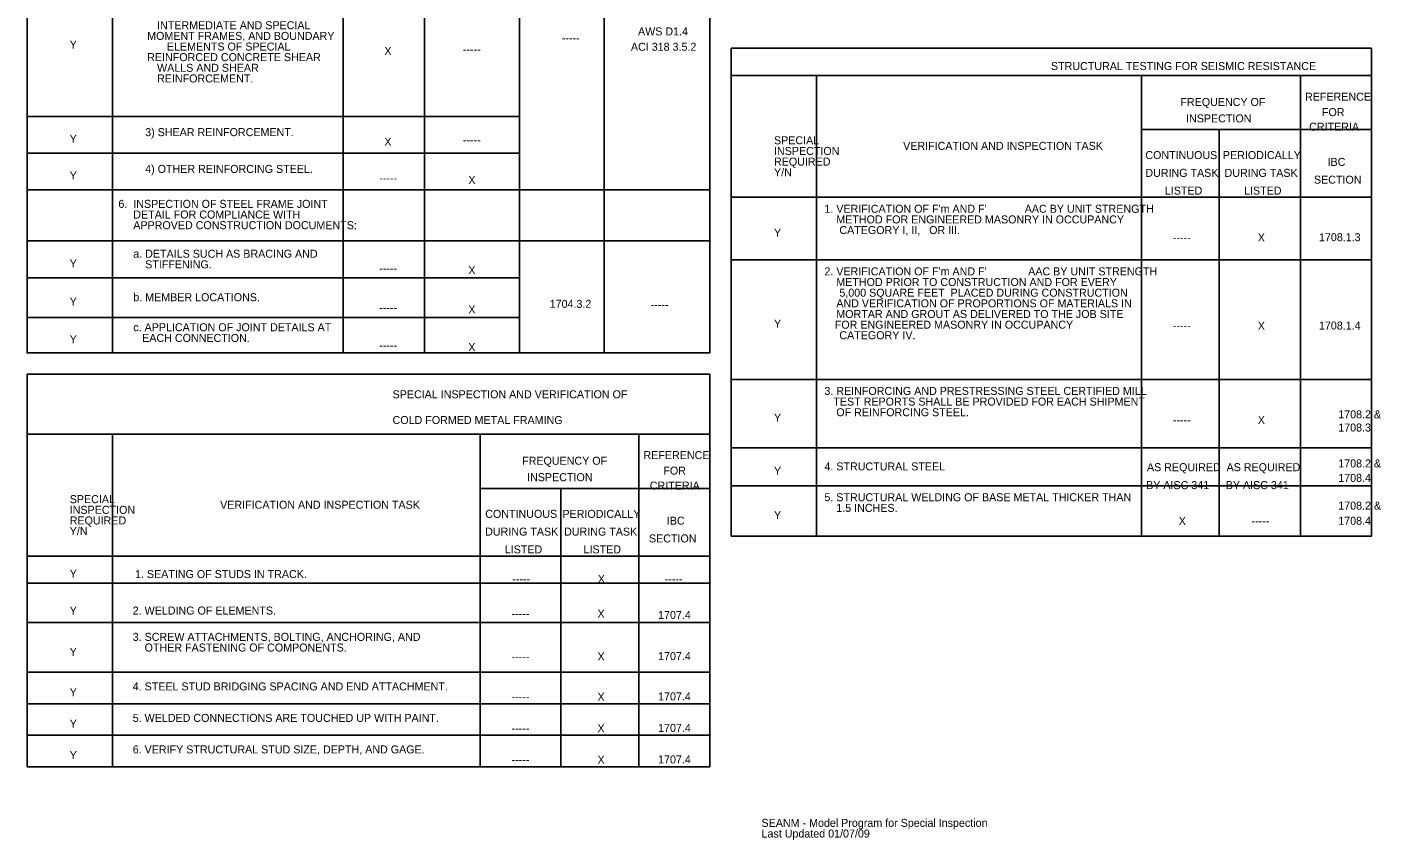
# Model space of a CAD drawing. Extents: x 2632118 to 2632142.4, y 1706724.1 to 1706788.4.
# Drawn here: x 2632128.03 to 2632142.13, y 1706769.54 to 1706778 of the extents above; entities that cross this region are included whole.
import ezdxf

# ---------------------------------------------------------------- set-up
doc = ezdxf.new("R2010")
doc.units = 0
doc.layers.add('Default', color=7, linetype='Continuous')

msp = doc.modelspace()

# ---------------------------------------------------------------- linework, layer by layer
at = {"layer": 'Default'}
for p, q in [((2632128.922, 1706788.071), (2632128.922, 1706774.611)), ((2632131.325, 1706788.071), (2632131.325, 1706774.611)), ((2632133.161, 1706774.611), (2632133.161, 1706788.071)), ((2632132.172, 1706787.789), (2632132.172, 1706774.611)), ((2632134.041, 1706787.789), (2632134.041, 1706774.611)), ((2632136.255, 1706777.502), (2632136.255, 1706772.703)), ((2632139.639, 1706777.502), (2632139.639, 1706772.703)), ((2632141.293, 1706777.502), (2632141.293, 1706772.703)), ((2632133.161, 1706777.074), (2632128.033, 1706777.074)), ((2632142.033, 1706776.937), (2632139.639, 1706776.937)), ((2632140.448, 1706776.937), (2632140.448, 1706772.703)), ((2632133.161, 1706776.692), (2632128.033, 1706776.692)), ((2632135.144, 1706776.31), (2632128.033, 1706776.31)), ((2632142.033, 1706776.232), (2632135.366, 1706776.232)), ((2632135.144, 1706775.777), (2632128.033, 1706775.777)), ((2632142.033, 1706775.58), (2632135.366, 1706775.58)), ((2632133.161, 1706775.393), (2632128.033, 1706775.393)), ((2632133.161, 1706774.981), (2632128.033, 1706774.981)), ((2632135.144, 1706774.389), (2632128.033, 1706774.389)), ((2632128.033, 1706774.389), (2632128.033, 1706770.303)), ((2632135.144, 1706770.303), (2632135.144, 1706774.389)), ((2632142.033, 1706774.335), (2632135.366, 1706774.335)), ((2632128.922, 1706773.765), (2632128.922, 1706770.303)), ((2632132.75, 1706773.765), (2632132.75, 1706770.303)), ((2632134.404, 1706773.765), (2632134.404, 1706770.303)), ((2632142.033, 1706773.623), (2632135.366, 1706773.623)), ((2632135.144, 1706773.201), (2632132.75, 1706773.201)), ((2632135.144, 1706773.201), (2632132.75, 1706773.201)), ((2632133.592, 1706773.201), (2632133.592, 1706770.303)), ((2632142.033, 1706773.227), (2632135.366, 1706773.227)), ((2632135.144, 1706772.496), (2632128.033, 1706772.496)), ((2632135.144, 1706772.213), (2632128.033, 1706772.213)), ((2632135.144, 1706771.803), (2632128.033, 1706771.803)), ((2632135.144, 1706771.287), (2632128.033, 1706771.287)), ((2632135.144, 1706770.959), (2632128.033, 1706770.959)), ((2632135.144, 1706770.631), (2632128.033, 1706770.631)), ((2632135.144, 1706770.631), (2632128.033, 1706770.631)), ((2632128.033, 1706770.303), (2632135.144, 1706770.303))]:
    msp.add_line(p, q, dxfattribs=at)
for points in [[(2632135.144, 1706774.611), (2632135.144, 1706788.353), (2632128.033, 1706788.353), (2632128.033, 1706774.611)], [(2632135.366, 1706772.703), (2632142.033, 1706772.703), (2632142.033, 1706777.784), (2632135.366, 1706777.784)]]:
    msp.add_lwpolyline(points, close=True, dxfattribs=at)
for points in [[(2632142.033, 1706777.502), (2632135.366, 1706777.502)], [(2632135.144, 1706773.765), (2632128.033, 1706773.765)]]:
    msp.add_lwpolyline(points, dxfattribs=at)

# ---------------------------------------------------------------- texts
for s, height, p in [('             INTERMEDIATE AND SPECIAL ', 0.08333, (2632128.984, 1706777.982)), ('             MOMENT FRAMES, AND BOUNDARY ', 0.08333, (2632128.881, 1706777.871)), ('AWS D1.4', 0.0833, (2632134.395, 1706777.918)), ('Y', 0.0833, (2632128.477, 1706777.781)), ('             ELEMENTS OF SPECIAL ', 0.08333, (2632129.086, 1706777.76)), ('X', 0.0833, (2632131.753, 1706777.714)), ('-----', 0.0833, (2632133.601, 1706777.851)), ('ACI 318 3.5.2', 0.08333, (2632134.321, 1706777.758)), ('             REINFORCED CONCRETE SHEAR ', 0.08333, (2632128.881, 1706777.65)), ('-----', 0.0833, (2632132.571, 1706777.732)), ('STRUCTURAL TESTING FOR SEISMIC RESISTANCE', 0.08333, (2632138.695, 1706777.557)), ('             WALLS AND SHEAR ', 0.08333, (2632128.984, 1706777.539)), ('             REINFORCEMENT. ', 0.08333, (2632128.984, 1706777.428)), ('FREQUENCY OF  ', 0.08333, (2632140.043, 1706777.183)), ('REFERENCE', 0.0833, (2632141.341, 1706777.238)), ('INSPECTION ', 0.08333, (2632140.102, 1706777.012)), ('FOR', 0.0833, (2632141.517, 1706777.077)), ('         3) SHEAR REINFORCEMENT.', 0.08333, (2632128.984, 1706776.869)), ('CRITERIA', 0.0833, (2632141.384, 1706776.925)), ('Y', 0.0833, (2632128.477, 1706776.8)), ('X', 0.0833, (2632131.753, 1706776.769)), ('-----', 0.0833, (2632132.571, 1706776.788)), ('SPECIAL ', 0.0833, (2632135.811, 1706776.784)), ('VERIFICATION AND INSPECTION TASK ', 0.08333, (2632137.156, 1706776.726)), ('REQUIRED', 0.0833, (2632135.811, 1706776.562)), ('INSPECTION ', 0.08333, (2632135.811, 1706776.673)), ('CONTINUOUS', 0.0833, (2632139.678, 1706776.63)), ('PERIODICALLY', 0.08333, (2632140.486, 1706776.63)), ('         4) OTHER REINFORCING STEEL.', 0.08333, (2632128.984, 1706776.486)), ('Y/N', 0.0833, (2632135.811, 1706776.451)), ('DURING TASK', 0.08333, (2632139.678, 1706776.445)), ('DURING TASK', 0.08333, (2632140.503, 1706776.445)), ('IBC', 0.0833, (2632141.576, 1706776.559)), ('Y', 0.0833, (2632128.477, 1706776.418)), ('-----', 0.0833, (2632131.7, 1706776.39)), ('X', 0.0833, (2632132.628, 1706776.371)), ('SECTION', 0.0833, (2632141.434, 1706776.374)), ('LISTED', 0.0833, (2632139.881, 1706776.26)), ('LISTED', 0.0833, (2632140.706, 1706776.26)), ('6.  INSPECTION OF STEEL FRAME JOINT ', 0.08333, (2632128.984, 1706776.122)), ('     DETAIL FOR COMPLIANCE WITH ', 0.08333, (2632128.984, 1706776.011)), ("1. VERIFICATION OF F'm AND F'", 0.08333, (2632136.336, 1706776.071)), ('AAC BY UNIT STRENGTH ', 0.08333, (2632138.422, 1706776.071)), ('     APPROVED CONSTRUCTION DOCUMENTS:', 0.08333, (2632128.984, 1706775.9)), ('    METHOD FOR ENGINEERED MASONRY IN OCCUPANCY', 0.08333, (2632136.336, 1706775.96)), ('Y', 0.0833, (2632135.811, 1706775.822)), ('    CATEGORY I, II,   OR III.', 0.08333, (2632136.368, 1706775.849)), ('-----', 0.0833, (2632139.965, 1706775.773)), ('X', 0.0833, (2632140.849, 1706775.773)), ('1708.1.3', 0.0833, (2632141.486, 1706775.775)), ('     a. DETAILS SUCH AS BRACING AND ', 0.08333, (2632128.984, 1706775.603)), ('Y', 0.0833, (2632128.477, 1706775.501)), ('         STIFFENING.', 0.08333, (2632128.984, 1706775.492)), ('-----', 0.0833, (2632131.7, 1706775.451)), ('X', 0.0833, (2632132.628, 1706775.432)), ("2. VERIFICATION OF F'm AND F'", 0.08333, (2632136.336, 1706775.419)), ('    METHOD PRIOR TO CONSTRUCTION AND FOR EVERY ', 0.08333, (2632136.336, 1706775.308)), ('AAC BY UNIT STRENGTH ', 0.08333, (2632138.458, 1706775.419)), ('     b. MEMBER LOCATIONS.', 0.08333, (2632128.984, 1706775.15)), ('    5,000 SQUARE FEET  PLACED DURING CONSTRUCTION ', 0.08333, (2632136.368, 1706775.197)), ('Y', 0.0833, (2632128.477, 1706775.104)), ('X', 0.0833, (2632132.628, 1706775.023)), ('1704.3.2', 0.0833, (2632133.475, 1706775.081)), ('-----', 0.0833, (2632134.527, 1706775.072)), ('    AND VERIFICATION OF PROPORTIONS OF MATERIALS IN ', 0.08333, (2632136.336, 1706775.086)), ('-----', 0.0833, (2632131.7, 1706775.043)), ('Y', 0.0833, (2632135.811, 1706774.874)), ('    MORTAR AND GROUT AS DELIVERED TO THE JOB SITE ', 0.08333, (2632136.336, 1706774.975)), ('     c. APPLICATION OF JOINT DETAILS AT ', 0.08333, (2632128.984, 1706774.837)), ('    FOR ENGINEERED MASONRY IN OCCUPANCY ', 0.08333, (2632136.32, 1706774.864)), ('    CATEGORY IV.', 0.08333, (2632136.368, 1706774.754)), ('-----', 0.0833, (2632139.965, 1706774.853)), ('X', 0.0833, (2632140.849, 1706774.853)), ('1708.1.4', 0.0833, (2632141.486, 1706774.855)), ('Y', 0.0833, (2632128.477, 1706774.713)), ('        EACH CONNECTION. ', 0.08333, (2632128.984, 1706774.726)), ('-----', 0.0833, (2632131.7, 1706774.649)), ('X', 0.0833, (2632132.628, 1706774.63)), ('3. REINFORCING AND PRESTRESSING STEEL CERTIFIED MILL', 0.08333, (2632136.336, 1706774.174)), ('SPECIAL INSPECTION AND VERIFICATION OF', 0.08333, (2632131.839, 1706774.139)), ('    TEST REPORTS SHALL BE PROVIDED FOR EACH SHIPMENT', 0.08333, (2632136.305, 1706774.063)), ('Y', 0.0833, (2632135.811, 1706773.896)), ('    OF REINFORCING STEEL.', 0.08333, (2632136.336, 1706773.952)), ('1708.2 &', 0.0833, (2632141.687, 1706773.93)), ('COLD FORMED METAL FRAMING', 0.08333, (2632131.839, 1706773.871)), ('-----', 0.0833, (2632139.965, 1706773.872)), ('X', 0.0833, (2632140.849, 1706773.872)), ('1708.3', 0.0833, (2632141.687, 1706773.793)), ('REFERENCE', 0.0833, (2632134.452, 1706773.506)), ('FREQUENCY OF  ', 0.08333, (2632133.188, 1706773.447)), ('FOR', 0.0833, (2632134.659, 1706773.344)), ('Y', 0.0833, (2632135.811, 1706773.342)), ('4. STRUCTURAL STEEL', 0.08333, (2632136.336, 1706773.388)), ('AS REQUIRED', 0.08333, (2632139.695, 1706773.38)), ('AS REQUIRED', 0.08333, (2632140.524, 1706773.38)), ('1708.2 &', 0.0833, (2632141.687, 1706773.419)), ('INSPECTION ', 0.08333, (2632133.24, 1706773.276)), ('CRITERIA', 0.0833, (2632134.518, 1706773.188)), ('BY AISC 341', 0.08333, (2632139.686, 1706773.193)), ('BY AISC 341', 0.08333, (2632140.515, 1706773.193)), ('1708.4', 0.0833, (2632141.687, 1706773.269)), ('SPECIAL ', 0.0833, (2632128.477, 1706773.047)), ('5. STRUCTURAL WELDING OF BASE METAL THICKER THAN', 0.08333, (2632136.336, 1706773.067)), ('INSPECTION ', 0.08333, (2632128.477, 1706772.936)), ('VERIFICATION AND INSPECTION TASK ', 0.08333, (2632130.043, 1706772.989)), ('    1.5 INCHES.', 0.08333, (2632136.336, 1706772.956)), ('1708.2 &', 0.0833, (2632141.687, 1706772.98)), ('REQUIRED', 0.0833, (2632128.477, 1706772.825)), ('CONTINUOUS', 0.0833, (2632132.804, 1706772.894)), ('PERIODICALLY', 0.08333, (2632133.608, 1706772.894)), ('IBC', 0.0833, (2632134.695, 1706772.823)), ('Y', 0.0833, (2632135.811, 1706772.882)), ('X', 0.0833, (2632140.026, 1706772.82)), ('-----', 0.0833, (2632140.784, 1706772.82)), ('1708.4', 0.0833, (2632141.687, 1706772.822)), ('Y/N', 0.0833, (2632128.477, 1706772.714)), ('DURING TASK', 0.08333, (2632132.803, 1706772.709)), ('DURING TASK', 0.08333, (2632133.625, 1706772.709)), ('SECTION', 0.0833, (2632134.509, 1706772.638)), ('LISTED', 0.0833, (2632133.007, 1706772.524)), ('LISTED', 0.0833, (2632133.828, 1706772.524)), ('Y', 0.0833, (2632128.477, 1706772.271)), ('1. SEATING OF STUDS IN TRACK.', 0.08333, (2632129.157, 1706772.267)), ('X', 0.0833, (2632133.976, 1706772.217)), ('-----', 0.0833, (2632133.086, 1706772.217)), ('-----', 0.0833, (2632134.673, 1706772.217)), ('Y', 0.0833, (2632128.477, 1706771.886)), ('2. WELDING OF ELEMENTS.', 0.08333, (2632129.133, 1706771.887)), ('-----', 0.0833, (2632133.078, 1706771.855)), ('X', 0.0833, (2632133.973, 1706771.855)), ('1707.4', 0.0833, (2632134.604, 1706771.841)), ('3. SCREW ATTACHMENTS, BOLTING, ANCHORING, AND', 0.08333, (2632129.133, 1706771.613)), ('    OTHER FASTENING OF COMPONENTS.', 0.08333, (2632129.133, 1706771.502)), ('Y', 0.0833, (2632128.477, 1706771.457)), ('-----', 0.0833, (2632133.078, 1706771.409)), ('X', 0.0833, (2632133.973, 1706771.409)), ('1707.4', 0.0833, (2632134.604, 1706771.413)), ('4. STEEL STUD BRIDGING SPACING AND END ATTACHMENT.', 0.08333, (2632129.133, 1706771.097)), ('Y', 0.0833, (2632128.477, 1706771.037)), ('-----', 0.0833, (2632133.078, 1706770.989)), ('X', 0.0833, (2632133.973, 1706770.989)), ('1707.4', 0.0833, (2632134.604, 1706770.993)), ('Y', 0.0833, (2632128.477, 1706770.709)), ('5. WELDED CONNECTIONS ARE TOUCHED UP WITH PAINT.', 0.08333, (2632129.133, 1706770.769)), ('X', 0.0833, (2632133.973, 1706770.661)), ('1707.4', 0.0833, (2632134.604, 1706770.665)), ('-----', 0.0833, (2632133.078, 1706770.661)), ('Y', 0.0833, (2632128.477, 1706770.382)), ('6. VERIFY STRUCTURAL STUD SIZE, DEPTH, AND GAGE.', 0.08333, (2632129.133, 1706770.441)), ('-----', 0.0833, (2632133.078, 1706770.334)), ('X', 0.0833, (2632133.973, 1706770.334)), ('1707.4', 0.0833, (2632134.604, 1706770.337)), ('SEANM - Model Program for Special Inspection ', 0.08333, (2632135.681, 1706769.676)), ('Last Updated 01/07/09', 0.08333, (2632135.681, 1706769.565))]:
    msp.add_text(s, height=height, dxfattribs=at).set_placement(p)

doc.saveas('drawing.dxf')
